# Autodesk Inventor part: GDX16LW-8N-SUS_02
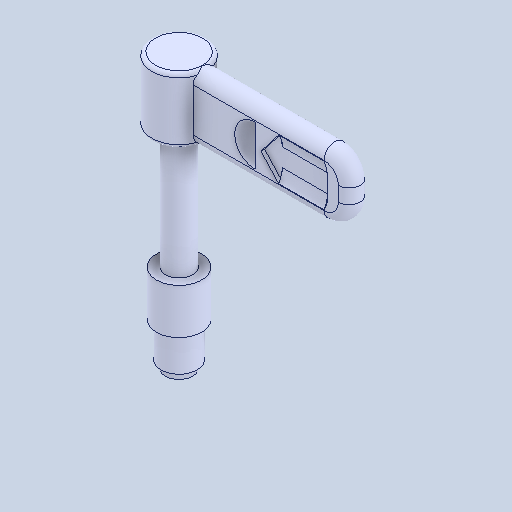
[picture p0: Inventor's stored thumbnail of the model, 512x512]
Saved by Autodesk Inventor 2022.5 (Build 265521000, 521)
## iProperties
Created: 2024-06
Part Number: GDX16LW-8N-SUS_02
Material: 一般
Document SubType Name: Modeling
Designer: ImaoCorp
Density: 1 g/cm^3
Appearance: 既定
Author: ImaoCorp
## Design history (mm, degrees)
feature "GDX16LW-8N-SUS_02"
node "ソリッド1"
